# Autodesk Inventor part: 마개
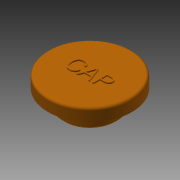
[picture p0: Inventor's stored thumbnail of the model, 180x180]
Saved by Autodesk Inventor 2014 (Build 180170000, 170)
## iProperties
Created: 2018-03
Part Number: 마개
Material: 고무
Document SubType Name: Modeling
Designer: mduedu
Density: 1 g/cm^3
Appearance: Orange
Author: mduedu
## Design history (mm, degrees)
sketch "스케치1"
  geometry: C1 r 17 at (0, 0); 1 further point
  constraints: 1 centre point, 1 coincident
  dimensions: "d21" = 34 diameter of C1
extrude "돌출1" new body sketch "스케치1" distance "d2" = 6; taper "d3" = 0 deg
fillet "모깎기4" dims "d22" = 1
sketch "스케치6"
  geometry: C1 r 11 at (0, 0); 1 further point
  constraints: 1 centre point, 1 coincident
  dimensions: "d23" = 22 diameter of C1
extrude "돌출5" join sketch "스케치6" distance "d24" = 6; taper "d25" = 0 deg
sketch "스케치7"
  geometry: C1 r 7.5 at (0, 0); 1 further point
  constraints: 1 centre point, 1 coincident
  dimensions: "d26" = 15 diameter of C1
extrude "돌출6" cut sketch "스케치7" distance "d27" = 6; taper "d28" = 0 deg
sketch "스케치8"
  geometry: C1 r 17 at (0, 0) reference; C2 r 14 at (0, 0); 1 further point
  constraints: 1 centre point, 1 coincident
  dimensions: "d37" = 28 diameter of C2
extrude "돌출7" cut sketch "스케치8" distance "d30" = 1; taper "d31" = 0 deg
fillet "모깎기5" dims "d32" = 1
chamfer "모따기2" distance "d33" = 1; stored, may be unused: second distance "d34" = 2, angle "d35" = 45 deg
sketch "스케치5"
  geometry: 2 further points
  constraints: 1 coincident, 1 other
feature "엠보싱1" sketch "스케치5" dims "d19" = 0.5, "d20" = 0
node "솔리드1"
